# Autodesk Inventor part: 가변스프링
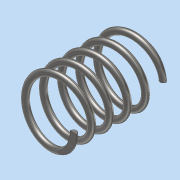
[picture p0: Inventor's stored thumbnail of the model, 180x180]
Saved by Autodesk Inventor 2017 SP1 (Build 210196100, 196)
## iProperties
Part Number: 가변스프링
Material: 스테인레스 스틸
Document SubType Name: Modeling
Designer: MRC
Density: 8 g/cm^3
Appearance: 반연마
Mass: 6.99701 g
Surface Area: 17.7559 cm^2
Volume: 0.874626 cm^3
Author: MRC
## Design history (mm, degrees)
sketch "스케치1"
  geometry: L1 (0, 0)-(9, 0); L2 (0, 0)-(0, 28.5); L3 (0, 28.5)-(9, 28.5); C1 r 1 at (9, 0)
  constraints: 6 end point, 2 horizontal, 1 centre point, 1 coincident, 1 vertical
  dimensions: "d0" = 9 distance of L1.start L1.end; "d1" = 28.49998 distance of L1.start L2.end (derived); "d2" = 9 distance of L2.end L3.end; "d3" = 2 diameter of C1
feature "코일1" pitch "d4" = 10; turns "d6" = 5; dims "d5" = 28.49998 (= d1), "d7" = 0, angle "d8" = 90 deg, angle "d9" = 90 deg, "d10" = 0, "d11" = 0
sketch "스케치2"
  geometry: L1 (28.5, 12.299)-(0, 12.299); L2 (0, 12.299)-(0, -12.299); L3 (0, -12.299)-(28.5, -12.299); L4 (28.5, -12.299)-(28.5, 12.299); 2 further points
  constraints: 8 end point, 2 parallel, 1 coincident, 1 horizontal, 1 midpoint, 1 perpendicular
  dimensions: "d12" = 28.49998 distance of L2.end L3.end (= d1)
extrude "돌출1" sketch "스케치2" stored distance "d13" = 0; taper "d14" = 0 deg
node "솔리드1"
